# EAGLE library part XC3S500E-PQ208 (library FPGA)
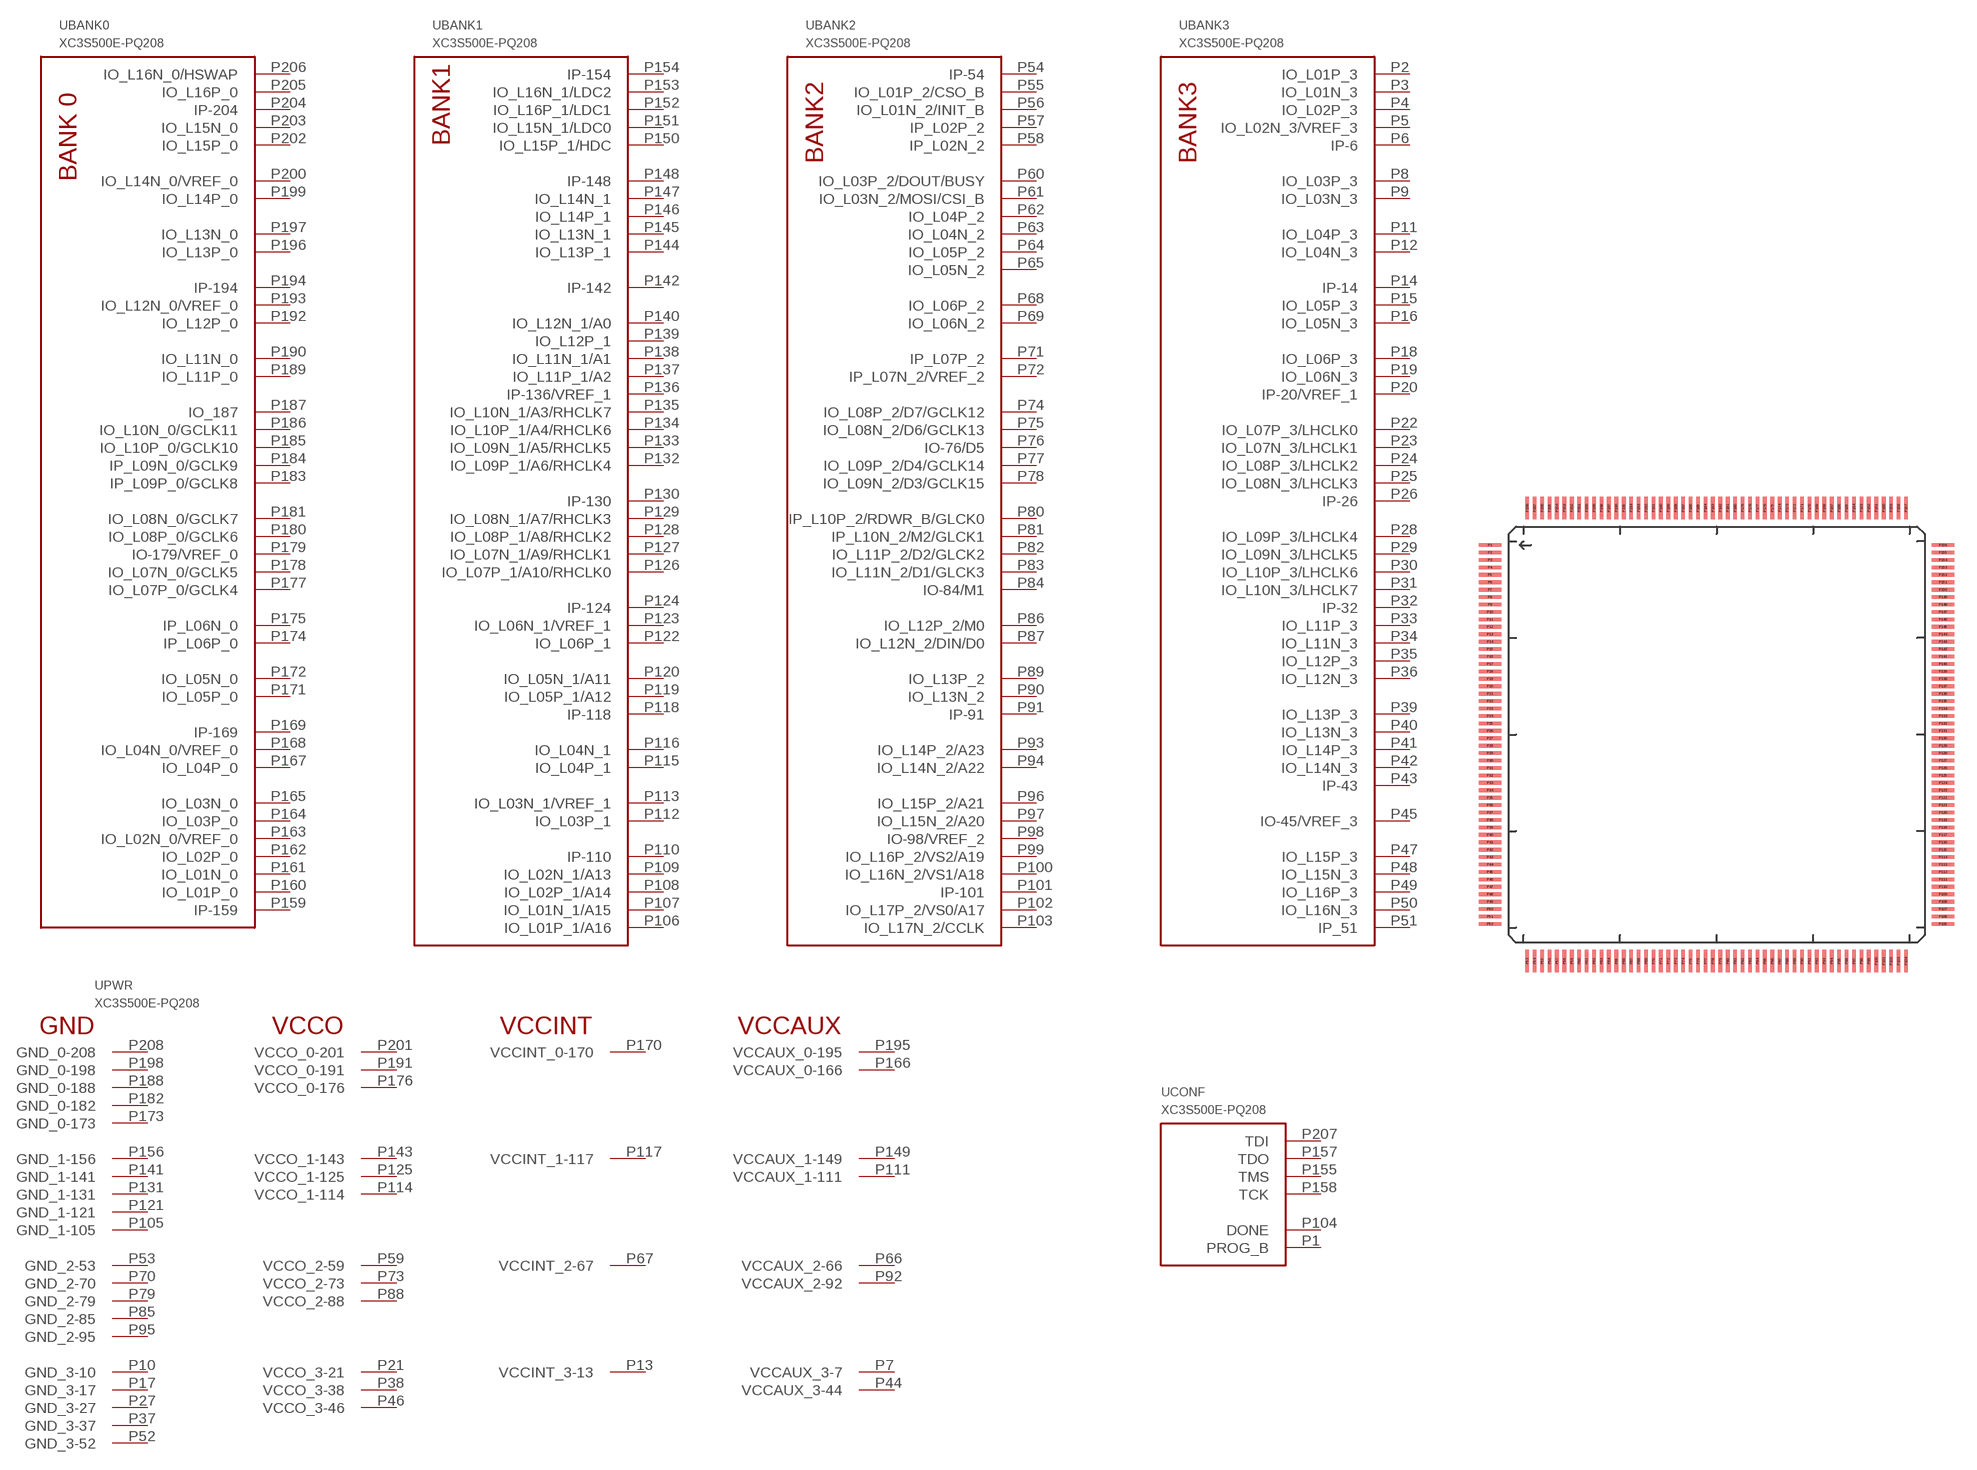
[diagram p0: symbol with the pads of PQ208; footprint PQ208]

Designator prefix U; gates BANK0=XC3S500E-PQ208-BANK0 BANK1=XC3S500E-PQ208-BANK1 BANK2=XC3S500E-PQ208-BANK2 BANK3=XC3S500E-PQ208-BANK3 CONF=XC3S500E-PQ208-CONF PWR=XC3S500E-PQ208-PWR

## XC3S500E-PQ208  [PQ208]
P1  CONF:PROG_B  in
P2  BANK3:IO_L01P_3
P3  BANK3:IO_L01N_3
P4  BANK3:IO_L02P_3
P5  BANK3:IO_L02N_3/VREF_3
P6  BANK3:IP-6  in
P7  PWR:VCCAUX_3-7  pwr
P8  BANK3:IO_L03P_3
P9  BANK3:IO_L03N_3
P10  PWR:GND_3-10  pwr
P11  BANK3:IO_L04P_3
P12  BANK3:IO_L04N_3
P13  PWR:VCCINT_3-13  pwr
P14  BANK3:IP-14  in
P15  BANK3:IO_L05P_3
P16  BANK3:IO_L05N_3
P17  PWR:GND_3-17  pwr
P18  BANK3:IO_L06P_3
P19  BANK3:IO_L06N_3
P20  BANK3:IP-20/VREF_1  in
P21  PWR:VCCO_3-21  pwr
P22  BANK3:IO_L07P_3/LHCLK0
P23  BANK3:IO_L07N_3/LHCLK1
P24  BANK3:IO_L08P_3/LHCLK2
P25  BANK3:IO_L08N_3/LHCLK3
P26  BANK3:IP-26  in
P27  PWR:GND_3-27  pwr
P28  BANK3:IO_L09P_3/LHCLK4
P29  BANK3:IO_L09N_3/LHCLK5
P30  BANK3:IO_L10P_3/LHCLK6
P31  BANK3:IO_L10N_3/LHCLK7
P32  BANK3:IP-32  in
P33  BANK3:IO_L11P_3
P34  BANK3:IO_L11N_3
P35  BANK3:IO_L12P_3
P36  BANK3:IO_L12N_3
P37  PWR:GND_3-37  pwr
P38  PWR:VCCO_3-38  pwr
P39  BANK3:IO_L13P_3
P40  BANK3:IO_L13N_3
P41  BANK3:IO_L14P_3
P42  BANK3:IO_L14N_3
P43  BANK3:IP-43  in
P44  PWR:VCCAUX_3-44  pwr
P45  BANK3:IO-45/VREF_3
P46  PWR:VCCO_3-46  pwr
P47  BANK3:IO_L15P_3
P48  BANK3:IO_L15N_3
P49  BANK3:IO_L16P_3
P50  BANK3:IO_L16N_3
P51  BANK3:IP_51  in
P52  PWR:GND_3-52  pwr
P53  PWR:GND_2-53  pwr
P54  BANK2:IP-54  in
P55  BANK2:IO_L01P_2/CSO_B
P56  BANK2:IO_L01N_2/INIT_B
P57  BANK2:IP_L02P_2  in
P58  BANK2:IP_L02N_2  in
P59  PWR:VCCO_2-59  pwr
P60  BANK2:IO_L03P_2/DOUT/BUSY
P61  BANK2:IO_L03N_2/MOSI/CSI_B
P62  BANK2:IO_L04P_2
P63  BANK2:IO_L04N_2
P64  BANK2:IO_L05P_2
P65  BANK2:IO_L05N_2
P66  PWR:VCCAUX_2-66  pwr
P67  PWR:VCCINT_2-67  pwr
P68  BANK2:IO_L06P_2
P69  BANK2:IO_L06N_2
P70  PWR:GND_2-70  pwr
P71  BANK2:IP_L07P_2  in
P72  BANK2:IP_L07N_2/VREF_2  in
P73  PWR:VCCO_2-73  pwr
P74  BANK2:IO_L08P_2/D7/GCLK12
P75  BANK2:IO_L08N_2/D6/GCLK13
P76  BANK2:IO-76/D5
P77  BANK2:IO_L09P_2/D4/GCLK14
P78  BANK2:IO_L09N_2/D3/GCLK15
P79  PWR:GND_2-79  pwr
P80  BANK2:IP_L10P_2/RDWR_B/GLCK0  in
P81  BANK2:IP_L10N_2/M2/GLCK1  in
P82  BANK2:IO_L11P_2/D2/GLCK2
P83  BANK2:IO_L11N_2/D1/GLCK3
P84  BANK2:IO-84/M1
P85  PWR:GND_2-85  pwr
P86  BANK2:IO_L12P_2/M0
P87  BANK2:IO_L12N_2/DIN/D0
P88  PWR:VCCO_2-88  pwr
P89  BANK2:IO_L13P_2
P90  BANK2:IO_L13N_2
P91  BANK2:IP-91
P92  PWR:VCCAUX_2-92  pwr
P93  BANK2:IO_L14P_2/A23
P94  BANK2:IO_L14N_2/A22
P95  PWR:GND_2-95  pwr
P96  BANK2:IO_L15P_2/A21
P97  BANK2:IO_L15N_2/A20
P98  BANK2:IO-98/VREF_2
P99  BANK2:IO_L16P_2/VS2/A19
P100  BANK2:IO_L16N_2/VS1/A18
P101  BANK2:IP-101
P102  BANK2:IO_L17P_2/VS0/A17
P103  BANK2:IO_L17N_2/CCLK
P104  CONF:DONE  out
P105  PWR:GND_1-105  pwr
P106  BANK1:IO_L01P_1/A16
P107  BANK1:IO_L01N_1/A15
P108  BANK1:IO_L02P_1/A14
P109  BANK1:IO_L02N_1/A13
P110  BANK1:IP-110  in
P111  PWR:VCCAUX_1-111  pwr
P112  BANK1:IO_L03P_1
P113  BANK1:IO_L03N_1/VREF_1
P114  PWR:VCCO_1-114  pwr
P115  BANK1:IO_L04P_1
P116  BANK1:IO_L04N_1
P117  PWR:VCCINT_1-117  pwr
P118  BANK1:IP-118  in
P119  BANK1:IO_L05P_1/A12
P120  BANK1:IO_L05N_1/A11
P121  PWR:GND_1-121  pwr
P122  BANK1:IO_L06P_1
P123  BANK1:IO_L06N_1/VREF_1
P124  BANK1:IP-124  in
P125  PWR:VCCO_1-125  pwr
P126  BANK1:IO_L07P_1/A10/RHCLK0
P127  BANK1:IO_L07N_1/A9/RHCLK1
P128  BANK1:IO_L08P_1/A8/RHCLK2
P129  BANK1:IO_L08N_1/A7/RHCLK3
P130  BANK1:IP-130  in
P131  PWR:GND_1-131  pwr
P132  BANK1:IO_L09P_1/A6/RHCLK4
P133  BANK1:IO_L09N_1/A5/RHCLK5
P134  BANK1:IO_L10P_1/A4/RHCLK6
P135  BANK1:IO_L10N_1/A3/RHCLK7
P136  BANK1:IP-136/VREF_1  in
P137  BANK1:IO_L11P_1/A2
P138  BANK1:IO_L11N_1/A1
P139  BANK1:IO_L12P_1
P140  BANK1:IO_L12N_1/A0
P141  PWR:GND_1-141  pwr
P142  BANK1:IP-142  in
P143  PWR:VCCO_1-143  pwr
P144  BANK1:IO_L13P_1
P145  BANK1:IO_L13N_1
P146  BANK1:IO_L14P_1
P147  BANK1:IO_L14N_1
P148  BANK1:IP-148  in
P149  PWR:VCCAUX_1-149  pwr
P150  BANK1:IO_L15P_1/HDC
P151  BANK1:IO_L15N_1/LDC0
P152  BANK1:IO_L16P_1/LDC1
P153  BANK1:IO_L16N_1/LDC2
P154  BANK1:IP-154  in
P155  CONF:TMS  in
P156  PWR:GND_1-156  pwr
P157  CONF:TDO  out
P158  CONF:TCK  in
P159  BANK0:IP-159  in
P160  BANK0:IO_L01P_0
P161  BANK0:IO_L01N_0
P162  BANK0:IO_L02P_0
P163  BANK0:IO_L02N_0/VREF_0
P164  BANK0:IO_L03P_0
P165  BANK0:IO_L03N_0
P166  PWR:VCCAUX_0-166  pwr
P167  BANK0:IO_L04P_0
P168  BANK0:IO_L04N_0/VREF_0
P169  BANK0:IP-169  in
P170  PWR:VCCINT_0-170  pwr
P171  BANK0:IO_L05P_0
P172  BANK0:IO_L05N_0
P173  PWR:GND_0-173  pwr
P174  BANK0:IP_L06P_0  in
P175  BANK0:IP_L06N_0  in
P176  PWR:VCCO_0-176  pwr
P177  BANK0:IO_L07P_0/GCLK4
P178  BANK0:IO_L07N_0/GCLK5
P179  BANK0:IO-179/VREF_0
P180  BANK0:IO_L08P_0/GCLK6
P181  BANK0:IO_L08N_0/GCLK7
P182  PWR:GND_0-182  pwr
P183  BANK0:IP_L09P_0/GCLK8  in
P184  BANK0:IP_L09N_0/GCLK9  in
P185  BANK0:IO_L10P_0/GCLK10
P186  BANK0:IO_L10N_0/GCLK11
P187  BANK0:IO_187
P188  PWR:GND_0-188  pwr
P189  BANK0:IO_L11P_0
P190  BANK0:IO_L11N_0
P191  PWR:VCCO_0-191  pwr
P192  BANK0:IO_L12P_0
P193  BANK0:IO_L12N_0/VREF_0
P194  BANK0:IP-194  in
P195  PWR:VCCAUX_0-195  pwr
P196  BANK0:IO_L13P_0
P197  BANK0:IO_L13N_0
P198  PWR:GND_0-198  pwr
P199  BANK0:IO_L14P_0
P200  BANK0:IO_L14N_0/VREF_0
P201  PWR:VCCO_0-201  pwr
P202  BANK0:IO_L15P_0
P203  BANK0:IO_L15N_0
P204  BANK0:IP-204  in
P205  BANK0:IO_L16P_0
P206  BANK0:IO_L16N_0/HSWAP
P207  CONF:TDI  in
P208  PWR:GND_0-208  pwr

## Footprint PQ208 (pad centres in mm)
smd 1.5 x 0.25: P1 -15.25,12.75; P2 -15.25,12.25; P3 -15.25,11.75; P4 -15.25,11.25; P5 -15.25,10.75; P6 -15.25,10.25; P7 -15.25,9.75; P8 -15.25,9.25; P9 -15.25,8.75; P10 -15.25,8.25; P11 -15.25,7.75; P12 -15.25,7.25; P13 -15.25,6.75; P14 -15.25,6.25; P15 -15.25,5.75; P16 -15.25,5.25; P17 -15.25,4.75; P18 -15.25,4.25; P19 -15.25,3.75; P20 -15.25,3.25; P21 -15.25,2.75; P22 -15.25,2.25; P23 -15.25,1.75; P24 -15.25,1.25; P25 -15.25,0.75; P26 -15.25,0.25; P27 -15.25,-0.25; P28 -15.25,-0.75; P29 -15.25,-1.25; P30 -15.25,-1.75; P31 -15.25,-2.25; P32 -15.25,-2.75; P33 -15.25,-3.25; P34 -15.25,-3.75; P35 -15.25,-4.25; P36 -15.25,-4.75; P37 -15.25,-5.25; P38 -15.25,-5.75; P39 -15.25,-6.25; P40 -15.25,-6.75; P41 -15.25,-7.25; P42 -15.25,-7.75; P43 -15.25,-8.25; P44 -15.25,-8.75; P45 -15.25,-9.25; P46 -15.25,-9.75; P47 -15.25,-10.25; P48 -15.25,-10.75; P49 -15.25,-11.25; P50 -15.25,-11.75; P51 -15.25,-12.25; P52 -15.25,-12.75; P105 15.25,-12.75; P106 15.25,-12.25; P107 15.25,-11.75; P108 15.25,-11.25; P109 15.25,-10.75; P110 15.25,-10.25; P111 15.25,-9.75; P112 15.25,-9.25; P113 15.25,-8.75; P114 15.25,-8.25; P115 15.25,-7.75; P116 15.25,-7.25; P117 15.25,-6.75; P118 15.25,-6.25; P119 15.25,-5.75; P120 15.25,-5.25; P121 15.25,-4.75; P122 15.25,-4.25; P123 15.25,-3.75; P124 15.25,-3.25; P125 15.25,-2.75; P126 15.25,-2.25; P127 15.25,-1.75; P128 15.25,-1.25; P129 15.25,-0.75; P130 15.25,-0.25; P131 15.25,0.25; P132 15.25,0.75; P133 15.25,1.25; P134 15.25,1.75; P135 15.25,2.25; P136 15.25,2.75; P137 15.25,3.25; P138 15.25,3.75; P139 15.25,4.25; P140 15.25,4.75; P141 15.25,5.25; P142 15.25,5.75; P143 15.25,6.25; P144 15.25,6.75; P145 15.25,7.25; P146 15.25,7.75; P147 15.25,8.25; P148 15.25,8.75; P149 15.25,9.25; P150 15.25,9.75; P151 15.25,10.25; P152 15.25,10.75; P153 15.25,11.25; P154 15.25,11.75; P155 15.25,12.25; P156 15.25,12.75
smd 0.25 x 1.5: P53 -12.75,-15.25; P54 -12.25,-15.25; P55 -11.75,-15.25; P56 -11.25,-15.25; P57 -10.75,-15.25; P58 -10.25,-15.25; P59 -9.75,-15.25; P60 -9.25,-15.25; P61 -8.75,-15.25; P62 -8.25,-15.25; P63 -7.75,-15.25; P64 -7.25,-15.25; P65 -6.75,-15.25; P66 -6.25,-15.25; P67 -5.75,-15.25; P68 -5.25,-15.25; P69 -4.75,-15.25; P70 -4.25,-15.25; P71 -3.75,-15.25; P72 -3.25,-15.25; P73 -2.75,-15.25; P74 -2.25,-15.25; P75 -1.75,-15.25; P76 -1.25,-15.25; P77 -0.75,-15.25; P78 -0.25,-15.25; P79 0.25,-15.25; P80 0.75,-15.25; P81 1.25,-15.25; P82 1.75,-15.25; P83 2.25,-15.25; P84 2.75,-15.25; P85 3.25,-15.25; P86 3.75,-15.25; P87 4.25,-15.25; P88 4.75,-15.25; P89 5.25,-15.25; P90 5.75,-15.25; P91 6.25,-15.25; P92 6.75,-15.25; P93 7.25,-15.25; P94 7.75,-15.25; P95 8.25,-15.25; P96 8.75,-15.25; P97 9.25,-15.25; P98 9.75,-15.25; P99 10.25,-15.25; P100 10.75,-15.25; P101 11.25,-15.25; P102 11.75,-15.25; P103 12.25,-15.25; P104 12.75,-15.25; P157 12.75,15.25; P158 12.25,15.25; P159 11.75,15.25; P160 11.25,15.25; P161 10.75,15.25; P162 10.25,15.25; P163 9.75,15.25; P164 9.25,15.25; P165 8.75,15.25; P166 8.25,15.25; P167 7.75,15.25; P168 7.25,15.25; P169 6.75,15.25; P170 6.25,15.25; P171 5.75,15.25; P172 5.25,15.25; P173 4.75,15.25; P174 4.25,15.25; P175 3.75,15.25; P176 3.25,15.25; P177 2.75,15.25; P178 2.25,15.25; P179 1.75,15.25; P180 1.25,15.25; P181 0.75,15.25; P182 0.25,15.25; P183 -0.25,15.25; P184 -0.75,15.25; P185 -1.25,15.25; P186 -1.75,15.25; P187 -2.25,15.25; P188 -2.75,15.25; P189 -3.25,15.25; P190 -3.75,15.25; P191 -4.25,15.25; P192 -4.75,15.25; P193 -5.25,15.25; P194 -5.75,15.25; P195 -6.25,15.25; P196 -6.75,15.25; P197 -7.25,15.25; P198 -7.75,15.25; P199 -8.25,15.25; P200 -8.75,15.25; P201 -9.25,15.25; P202 -9.75,15.25; P203 -10.25,15.25; P204 -10.75,15.25; P205 -11.25,15.25; P206 -11.75,15.25; P207 -12.25,15.25; P208 -12.75,15.25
